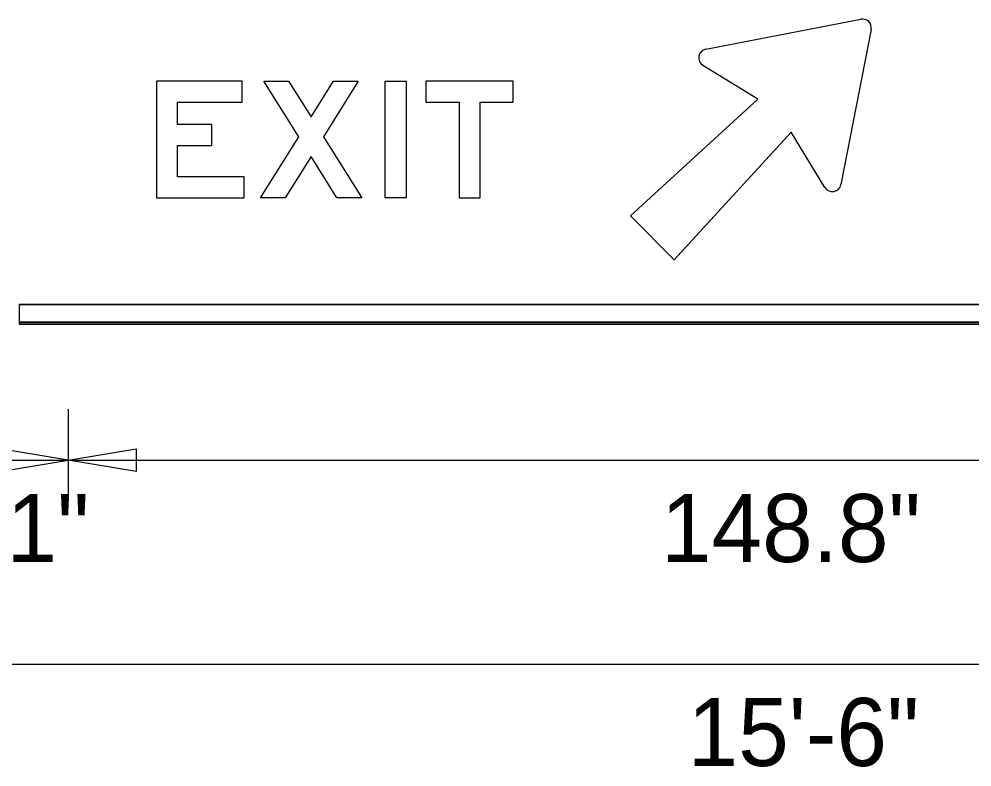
# Model space of a CAD drawing. Extents: x 2149934 to 2150188, y 145113 to 145238.
# Drawn here: x 2150091.28 to 2150099.45, y 145139.08 to 145145.5 of the extents above; entities that cross this region are included whole.
import ezdxf

# ---------------------------------------------------------------- set-up
doc = ezdxf.new("R2010")
doc.units = 0
for name, color, linetype in [('GSBWFILL', 7, 'Continuous'), ('GSCOLORFILL', 7, 'Continuous'), ('GSDIMS', 7, 'Continuous'), ('GSOUTLINE', 7, 'Continuous')]:
    doc.layers.add(name, color=color, linetype=linetype)

msp = doc.modelspace()

# ---------------------------------------------------------------- linework, layer by layer
at = {"layer": 'GSBWFILL'}
for p, q in [((2150091.2786, 145143.0496), (2150104.7786, 145143.0496)), ((2150104.7786, 145143.0496), (2150091.2803, 145143.0496)), ((2150091.2803, 145143.0496), (2150091.2803, 145142.8829)), ((2150104.7786, 145142.8829), (2150091.2786, 145142.8829)), ((2150091.2786, 145142.8829), (2150104.7786, 145142.8829)), ((2150091.2803, 145142.8829), (2150104.7786, 145142.8829))]:
    msp.add_line(p, q, dxfattribs=at)
for points in [[(2150097.1701, 145145.2404), (2150098.5007, 145145.4985)], [(2150098.5886, 145145.4106), (2150098.3305, 145144.0801)], [(2150098.1929, 145144.0552), (2150097.9033, 145144.528), (2150096.9004, 145143.4332), (2150096.5233, 145143.8103), (2150097.6181, 145144.8132), (2150097.1452, 145145.1028)]]:
    msp.add_lwpolyline(points, dxfattribs=at)
for points in [[(2150093.209, 145144.1465), (2150092.639, 145144.1465), (2150092.639, 145144.4155), (2150092.934, 145144.4155), (2150092.934, 145144.5955), (2150092.639, 145144.5955), (2150092.639, 145144.7865), (2150093.194, 145144.7865), (2150093.194, 145144.9665), (2150092.459, 145144.9665), (2150092.459, 145143.9665), (2150093.209, 145143.9665)], [(2150094.0065, 145143.9665), (2150093.784, 145144.3211), (2150093.5615, 145143.9665), (2150093.349, 145143.9665), (2150093.6777, 145144.4904), (2150093.379, 145144.9665), (2150093.5915, 145144.9665), (2150093.784, 145144.6597), (2150093.9765, 145144.9665), (2150094.189, 145144.9665), (2150093.8902, 145144.4904), (2150094.219, 145143.9665)], [(2150094.419, 145143.9665), (2150094.419, 145144.9665), (2150094.599, 145144.9665), (2150094.599, 145143.9665)], [(2150094.769, 145144.7865), (2150095.054, 145144.7865), (2150095.054, 145143.9665), (2150095.234, 145143.9665), (2150095.234, 145144.7865), (2150095.519, 145144.7865), (2150095.519, 145144.9665), (2150094.769, 145144.9665)]]:
    msp.add_lwpolyline(points, close=True, dxfattribs=at)
for centre, start, end in [((2150098.515, 145145.4249), 349.02227, 100.97773), ((2150097.1844, 145145.1668), 100.97773, 238.51547), ((2150098.2569, 145144.0943), 211.48453, 349.02227)]:
    msp.add_arc(centre, 0.075, start, end, dxfattribs=at)
at = {"layer": 'GSCOLORFILL'}
for p, q in [((2150091.2786, 145143.0496), (2150104.7786, 145143.0496)), ((2150104.7786, 145143.0496), (2150091.2803, 145143.0496)), ((2150091.2803, 145143.0496), (2150091.2803, 145142.8829)), ((2150091.2786, 145142.8996), (2150104.7786, 145142.8996)), ((2150091.2786, 145142.8829), (2150104.7786, 145142.8829)), ((2150091.2786, 145142.8829), (2150104.7786, 145142.8829)), ((2150104.7786, 145142.8829), (2150091.2786, 145142.8829)), ((2150104.7786, 145142.8829), (2150091.2786, 145142.8829)), ((2150104.7786, 145142.8996), (2150091.2788, 145142.8996)), ((2150091.2788, 145142.8996), (2150091.2788, 145142.8829)), ((2150091.2788, 145142.8829), (2150104.7786, 145142.8829)), ((2150091.2803, 145142.8829), (2150104.7786, 145142.8829))]:
    msp.add_line(p, q, dxfattribs=at)
for points in [[(2150097.1701, 145145.2404), (2150098.5007, 145145.4985)], [(2150098.5886, 145145.4106), (2150098.3305, 145144.0801)], [(2150098.1929, 145144.0552), (2150097.9033, 145144.528), (2150096.9004, 145143.4332), (2150096.5233, 145143.8103), (2150097.6181, 145144.8132), (2150097.1452, 145145.1028)]]:
    msp.add_lwpolyline(points, dxfattribs=at)
for points in [[(2150093.209, 145144.1465), (2150092.639, 145144.1465), (2150092.639, 145144.4155), (2150092.934, 145144.4155), (2150092.934, 145144.5955), (2150092.639, 145144.5955), (2150092.639, 145144.7865), (2150093.194, 145144.7865), (2150093.194, 145144.9665), (2150092.459, 145144.9665), (2150092.459, 145143.9665), (2150093.209, 145143.9665)], [(2150094.0065, 145143.9665), (2150093.784, 145144.3211), (2150093.5615, 145143.9665), (2150093.349, 145143.9665), (2150093.6777, 145144.4904), (2150093.379, 145144.9665), (2150093.5915, 145144.9665), (2150093.784, 145144.6597), (2150093.9765, 145144.9665), (2150094.189, 145144.9665), (2150093.8902, 145144.4904), (2150094.219, 145143.9665)], [(2150094.419, 145143.9665), (2150094.419, 145144.9665), (2150094.599, 145144.9665), (2150094.599, 145143.9665)], [(2150094.769, 145144.7865), (2150095.054, 145144.7865), (2150095.054, 145143.9665), (2150095.234, 145143.9665), (2150095.234, 145144.7865), (2150095.519, 145144.7865), (2150095.519, 145144.9665), (2150094.769, 145144.9665)]]:
    msp.add_lwpolyline(points, close=True, dxfattribs=at)
for centre, start, end in [((2150098.515, 145145.4249), 349.02227, 100.97773), ((2150097.1844, 145145.1668), 100.97773, 238.51547), ((2150098.2569, 145144.0943), 211.48453, 349.02227)]:
    msp.add_arc(centre, 0.075, start, end, dxfattribs=at)
at = {"layer": 'GSDIMS'}
for p, q in [((2150091.7002, 145142.1537), (2150091.7002, 145141.4246)), ((2150091.7002, 145142.1537), (2150091.7002, 145141.4246)), ((2150090.2786, 145141.7162), (2150091.7002, 145141.7162)), ((2150091.7002, 145141.7162), (2150104.102, 145141.7162)), ((2150090.2786, 145139.9662), (2150105.7787, 145139.9662))]:
    msp.add_line(p, q, dxfattribs=at)
for points in [[(2150091.7002, 145141.7162), (2150091.1169, 145141.8135), (2150091.1169, 145141.619)], [(2150091.7002, 145141.7162), (2150092.2835, 145141.8135), (2150092.2835, 145141.619)]]:
    msp.add_lwpolyline(points, close=True, dxfattribs=at)
at = {"layer": 'GSOUTLINE'}
for p, q in [((2150091.2786, 145143.0496), (2150104.7786, 145143.0496)), ((2150091.2786, 145143.0496), (2150104.7786, 145143.0496)), ((2150091.2786, 145142.8829), (2150104.7786, 145142.8829)), ((2150104.7786, 145142.8829), (2150091.2786, 145142.8829)), ((2150091.2786, 145142.8829), (2150104.7786, 145142.8829))]:
    msp.add_line(p, q, dxfattribs=at)
for points in [[(2150097.1701, 145145.2404), (2150098.5007, 145145.4985)], [(2150098.5886, 145145.4106), (2150098.3305, 145144.0801)], [(2150098.1929, 145144.0552), (2150097.9033, 145144.528), (2150096.9004, 145143.4332), (2150096.5233, 145143.8103), (2150097.6181, 145144.8132), (2150097.1452, 145145.1028)]]:
    msp.add_lwpolyline(points, dxfattribs=at)
for points in [[(2150093.209, 145144.1465), (2150092.639, 145144.1465), (2150092.639, 145144.4155), (2150092.934, 145144.4155), (2150092.934, 145144.5955), (2150092.639, 145144.5955), (2150092.639, 145144.7865), (2150093.194, 145144.7865), (2150093.194, 145144.9665), (2150092.459, 145144.9665), (2150092.459, 145143.9665), (2150093.209, 145143.9665)], [(2150094.0065, 145143.9665), (2150093.784, 145144.3211), (2150093.5615, 145143.9665), (2150093.349, 145143.9665), (2150093.6777, 145144.4904), (2150093.379, 145144.9665), (2150093.5915, 145144.9665), (2150093.784, 145144.6597), (2150093.9765, 145144.9665), (2150094.189, 145144.9665), (2150093.8902, 145144.4904), (2150094.219, 145143.9665)], [(2150094.419, 145143.9665), (2150094.419, 145144.9665), (2150094.599, 145144.9665), (2150094.599, 145143.9665)], [(2150094.769, 145144.7865), (2150095.054, 145144.7865), (2150095.054, 145143.9665), (2150095.234, 145143.9665), (2150095.234, 145144.7865), (2150095.519, 145144.7865), (2150095.519, 145144.9665), (2150094.769, 145144.9665)]]:
    msp.add_lwpolyline(points, close=True, dxfattribs=at)
for centre, start, end in [((2150098.515, 145145.4249), 349.02227, 100.97773), ((2150097.1844, 145145.1668), 100.97773, 238.51547), ((2150098.2569, 145144.0943), 211.48453, 349.02227)]:
    msp.add_arc(centre, 0.075, start, end, dxfattribs=at)

# ---------------------------------------------------------------- texts
at = {"layer": 'GSDIMS'}
for s, p in [('17.1"', (2150090.0871, 145140.8412)), ('148.8"', (2150096.7863, 145140.8412)), ('15\'-6"', (2150097.0145, 145139.0912))]:
    msp.add_text(s, height=0.58333, dxfattribs=at).set_placement(p)

doc.saveas('drawing.dxf')
